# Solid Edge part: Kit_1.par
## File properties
Sűrűség: 0,000 kg/m^3
Pontosság: 0,990
Author: bmolnar
Last saved by: bmolnar
Revision: 78
Username: bmolnar
Dokumentum tartalom típus: 0
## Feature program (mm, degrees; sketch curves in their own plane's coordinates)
base feature "unnamed BaseFeature 1"
sketch for "unnamed Hole 1" plane through (17.575, -12.675, 4.5) normal (0, 0, -1) x-axis (0.38075, 0.924678, 0)
  hole centre (-3.8102, 0.136) bore radius 2.4585
hole "unnamed Hole 1" through
sketch for "unnamed Hole 2" plane through (17.575, -12.675, 4.5) normal (0, 0, -1) x-axis (0.38075, 0.924678, 0)
  hole centre (26.2418, -12.2384) bore radius 2.4585
hole "unnamed Hole 2" through
sketch for "unnamed Hole 3" plane through (17.575, -12.675, 4.5) normal (0, 0, -1) x-axis (0.38075, 0.924678, 0)
  hole centre (13.8675, -42.2904) bore radius 2.4585
hole "unnamed Hole 3" through
sketch for "unnamed Hole 4" plane through (17.575, -12.675, 4.5) normal (0, 0, -1) x-axis (0.38075, 0.924678, 0)
  hole centre (-16.1846, -29.9161) bore radius 2.4585
hole "unnamed Hole 4" through
pattern "unnamed Pattern 1" of "unnamed Hole 1", "unnamed Hole 2", "unnamed Hole 3", "unnamed Hole 4"
thread "unnamed Thread 1"
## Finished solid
Body 1: solid body, 293 faces, 721 edges, 450 vertices, 4 internal voids.
  Faces by surface: plane 140, cylinder 68, swept 55, torus 20, cone 9, spline 1
  Edges by curve: line 433, circle 161, spline 122, curve on surface 4, intersection 1
Bounding box of the edges (mm; curved faces can reach further): 49.000 x 49.000 x 14.100, from (-24.5, -24.5, 0) to (24.5, 24.5, 14.1).
Cylindrical faces by radius (mm): R0.2 x30, R0.335 x1, R0.5307 x1, R1.25 x1, R2.4585 x4, R2.5402 x12, R2.6 x4, R3.75 x4, R4 x4, R4.283 x1, R4.5 x5, R10.6633 x1
Conical faces (half-angle, radius in mm at the cone's reference point): 0.5 deg R8 x4, 45 deg R2.8085 x4, 45 deg R4.65 x1
Toroidal faces (ring radius, tube radius in mm): R2.9402 r0.4 x12, R3.55 r0.2 x8
Planar faces by outward normal: +x 12, +y 12, +z 1, -x 10, -y 12, -z 18, oblique 75
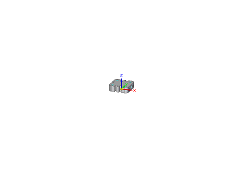
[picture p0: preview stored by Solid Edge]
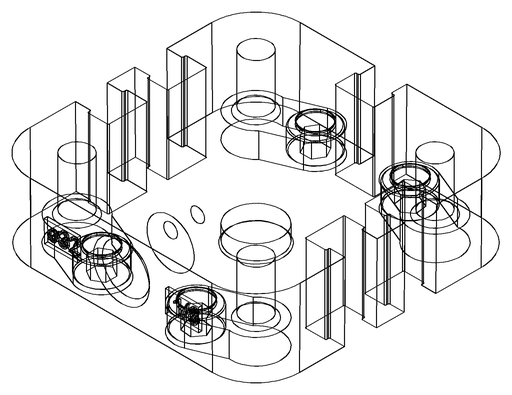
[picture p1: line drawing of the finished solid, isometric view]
